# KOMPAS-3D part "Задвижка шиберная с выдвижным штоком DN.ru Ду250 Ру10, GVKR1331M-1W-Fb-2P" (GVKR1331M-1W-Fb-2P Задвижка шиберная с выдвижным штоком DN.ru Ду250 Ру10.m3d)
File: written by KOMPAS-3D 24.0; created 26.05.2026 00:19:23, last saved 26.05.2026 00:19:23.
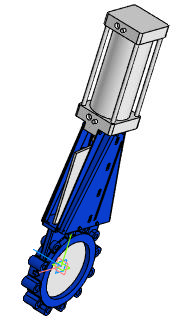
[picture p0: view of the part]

Document properties: Автор: R2D2; Полное имя файла: E:\Работа\Зайцев\GVKR1331M-1W-Fb-2P Задвижка шиберная с выдвижным штоком DN.ru Ду50-300 Ру16-10-6 с пневмоприводом\исходные материалы\DN250\DN250\GVKR1331M-1W-Fb-2P Задвижка шиберная с выдвижным штоком DN.ru Ду250 Ру10.m3d

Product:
- Part/product: Задвижка шиберная с выдвижным штоком DN.ru Ду250 Ру10  | designation GVKR1331M-1W-Fb-2P
    Масса: 51
    Раздел спецификации: Прочие изделия
    Примечание: D040-08798

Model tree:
1. Операция без истории:1

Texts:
  GVKR1331M-1W-Fb-2P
